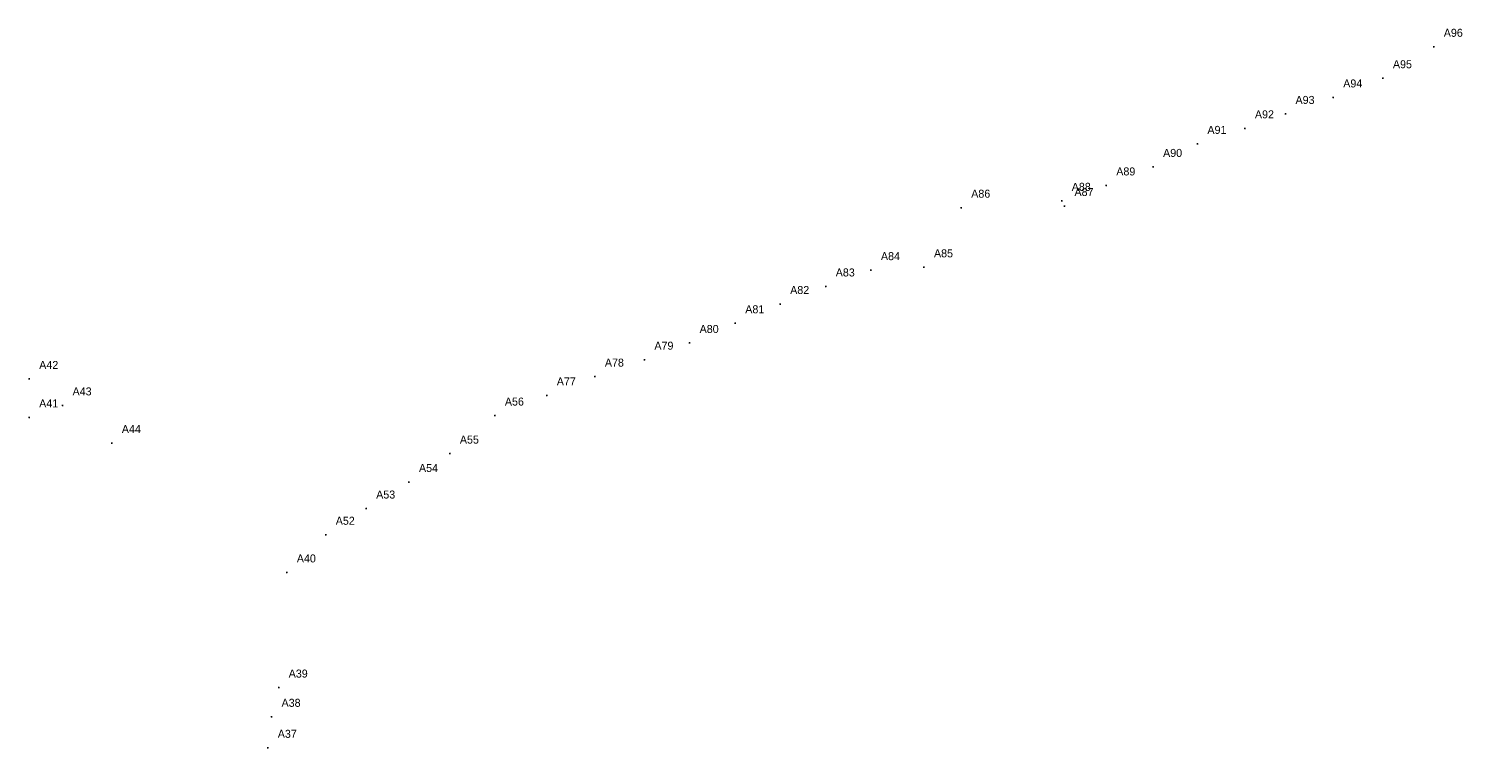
# Model space of a CAD drawing. Extents: x 1727960 to 1749562, y 651707 to 653731.
# Drawn here: x 1746276 to 1746993, y 652078 to 652437 of the extents above; entities that cross this region are included whole.
import ezdxf

# ---------------------------------------------------------------- set-up
doc = ezdxf.new("R2010")
doc.units = 0
doc.layers.add('SURVEY - DRAINAGE - Storm Sewer - Points - Locators', color=7, linetype='Continuous')
doc.layers.add('SURVEY - DRAINAGE - Storm Sewer - Points - Numbers', color=7, linetype='Continuous')

msp = doc.modelspace()

# ---------------------------------------------------------------- linework, layer by layer
at = {"layer": 'SURVEY - DRAINAGE - Storm Sewer - Points - Locators'}
for p, q in [((1746979.01, 652428.32), (1746978.51, 652428.32)), ((1746978.76, 652428.07), (1746978.76, 652428.57)), ((1746978.76, 652428.32), (1746978.76, 652428.32)), ((1746978.76, 652428.32), (1746978.76, 652428.32)), ((1746953.59, 652412.6), (1746953.09, 652412.6)), ((1746953.34, 652412.35), (1746953.34, 652412.85)), ((1746953.34, 652412.6), (1746953.34, 652412.6)), ((1746953.34, 652412.6), (1746953.34, 652412.6)), ((1746928.75, 652403.01), (1746928.25, 652403.01)), ((1746928.5, 652402.76), (1746928.5, 652403.26)), ((1746928.5, 652403.01), (1746928.5, 652403.01)), ((1746928.5, 652403.01), (1746928.5, 652403.01)), ((1746904.89, 652394.77), (1746904.39, 652394.77)), ((1746904.64, 652394.52), (1746904.64, 652395.02)), ((1746904.64, 652394.77), (1746904.64, 652394.77)), ((1746904.64, 652394.77), (1746904.64, 652394.77)), ((1746884.59, 652387.56), (1746884.09, 652387.56)), ((1746884.34, 652387.31), (1746884.34, 652387.81)), ((1746884.34, 652387.56), (1746884.34, 652387.56)), ((1746884.34, 652387.56), (1746884.34, 652387.56)), ((1746860.84, 652379.8), (1746860.34, 652379.8)), ((1746860.59, 652379.55), (1746860.59, 652380.05)), ((1746860.59, 652379.8), (1746860.59, 652379.8)), ((1746860.59, 652379.8), (1746860.59, 652379.8)), ((1746838.68, 652368.28), (1746838.18, 652368.28)), ((1746838.43, 652368.03), (1746838.43, 652368.53)), ((1746838.43, 652368.28), (1746838.43, 652368.28)), ((1746838.43, 652368.28), (1746838.43, 652368.28)), ((1746815.27, 652359.03), (1746814.77, 652359.03)), ((1746815.02, 652358.78), (1746815.02, 652359.28)), ((1746815.02, 652359.03), (1746815.02, 652359.03)), ((1746815.02, 652359.03), (1746815.02, 652359.03)), ((1746742.75, 652347.9), (1746742.25, 652347.9)), ((1746742.5, 652347.65), (1746742.5, 652348.15)), ((1746742.5, 652347.9), (1746742.5, 652347.9)), ((1746742.5, 652347.9), (1746742.5, 652347.9)), ((1746793.01, 652351.33), (1746792.51, 652351.33)), ((1746792.76, 652351.08), (1746792.76, 652351.58)), ((1746792.76, 652351.33), (1746792.76, 652351.33)), ((1746792.76, 652351.33), (1746792.76, 652351.33)), ((1746794.38, 652348.75), (1746793.88, 652348.75)), ((1746794.13, 652348.5), (1746794.13, 652349)), ((1746794.13, 652348.75), (1746794.13, 652348.75)), ((1746794.13, 652348.75), (1746794.13, 652348.75)), ((1746697.36, 652316.44), (1746697.36, 652316.94)), ((1746724.13, 652318.1), (1746723.63, 652318.1)), ((1746723.88, 652317.85), (1746723.88, 652318.35)), ((1746723.88, 652318.1), (1746723.88, 652318.1)), ((1746723.88, 652318.1), (1746723.88, 652318.1)), ((1746697.61, 652316.69), (1746697.11, 652316.69)), ((1746697.36, 652316.69), (1746697.36, 652316.69)), ((1746697.36, 652316.69), (1746697.36, 652316.69)), ((1746675.01, 652308.54), (1746674.51, 652308.54)), ((1746674.76, 652308.29), (1746674.76, 652308.79)), ((1746674.76, 652308.54), (1746674.76, 652308.54)), ((1746674.76, 652308.54), (1746674.76, 652308.54)), ((1746652.23, 652299.76), (1746651.73, 652299.76)), ((1746651.98, 652299.51), (1746651.98, 652300.01)), ((1746651.98, 652299.76), (1746651.98, 652299.76)), ((1746651.98, 652299.76), (1746651.98, 652299.76)), ((1746629.78, 652290.14), (1746629.28, 652290.14)), ((1746629.53, 652289.89), (1746629.53, 652290.39)), ((1746629.53, 652290.14), (1746629.53, 652290.14)), ((1746629.53, 652290.14), (1746629.53, 652290.14)), ((1746606.96, 652280.28), (1746606.46, 652280.28)), ((1746606.71, 652280.03), (1746606.71, 652280.53)), ((1746606.71, 652280.28), (1746606.71, 652280.28)), ((1746606.71, 652280.28), (1746606.71, 652280.28)), ((1746584.34, 652271.93), (1746583.84, 652271.93)), ((1746584.09, 652271.68), (1746584.09, 652272.18)), ((1746584.09, 652271.93), (1746584.09, 652271.93)), ((1746584.09, 652271.93), (1746584.09, 652271.93)), ((1746276.77, 652262.3), (1746276.27, 652262.3)), ((1746276.52, 652262.05), (1746276.52, 652262.55)), ((1746276.52, 652262.3), (1746276.52, 652262.3)), ((1746276.52, 652262.3), (1746276.52, 652262.3)), ((1746559.58, 652263.47), (1746559.08, 652263.47)), ((1746559.33, 652263.22), (1746559.33, 652263.72)), ((1746559.33, 652263.47), (1746559.33, 652263.47)), ((1746559.33, 652263.47), (1746559.33, 652263.47)), ((1746535.55, 652254.08), (1746535.05, 652254.08)), ((1746535.3, 652253.83), (1746535.3, 652254.33)), ((1746535.3, 652254.08), (1746535.3, 652254.08)), ((1746535.3, 652254.08), (1746535.3, 652254.08)), ((1746293.44, 652249.08), (1746292.94, 652249.08)), ((1746293.19, 652248.83), (1746293.19, 652249.33)), ((1746293.19, 652249.08), (1746293.19, 652249.08)), ((1746293.19, 652249.08), (1746293.19, 652249.08)), ((1746276.75, 652243.08), (1746276.25, 652243.08)), ((1746276.5, 652242.83), (1746276.5, 652243.33)), ((1746276.5, 652243.08), (1746276.5, 652243.08)), ((1746276.5, 652243.08), (1746276.5, 652243.08)), ((1746509.59, 652244), (1746509.09, 652244)), ((1746509.34, 652243.75), (1746509.34, 652244.25)), ((1746509.34, 652244), (1746509.34, 652244)), ((1746509.34, 652244), (1746509.34, 652244)), ((1746318.07, 652230.29), (1746317.57, 652230.29)), ((1746317.82, 652230.04), (1746317.82, 652230.54)), ((1746317.82, 652230.29), (1746317.82, 652230.29)), ((1746317.82, 652230.29), (1746317.82, 652230.29)), ((1746487.09, 652224.99), (1746486.59, 652224.99)), ((1746486.84, 652224.74), (1746486.84, 652225.24)), ((1746486.84, 652224.99), (1746486.84, 652224.99)), ((1746486.84, 652224.99), (1746486.84, 652224.99)), ((1746466.64, 652210.79), (1746466.14, 652210.79)), ((1746466.39, 652210.54), (1746466.39, 652211.04)), ((1746466.39, 652210.79), (1746466.39, 652210.79)), ((1746466.39, 652210.79), (1746466.39, 652210.79)), ((1746445.24, 652197.53), (1746444.74, 652197.53)), ((1746444.99, 652197.28), (1746444.99, 652197.78)), ((1746444.99, 652197.53), (1746444.99, 652197.53)), ((1746444.99, 652197.53), (1746444.99, 652197.53)), ((1746425.03, 652184.43), (1746424.53, 652184.43)), ((1746424.78, 652184.18), (1746424.78, 652184.68)), ((1746424.78, 652184.43), (1746424.78, 652184.43)), ((1746424.78, 652184.43), (1746424.78, 652184.43)), ((1746405.57, 652165.61), (1746405.07, 652165.61)), ((1746405.32, 652165.36), (1746405.32, 652165.86)), ((1746405.32, 652165.61), (1746405.32, 652165.61)), ((1746405.32, 652165.61), (1746405.32, 652165.61)), ((1746401.5, 652108.05), (1746401, 652108.05)), ((1746401.25, 652107.8), (1746401.25, 652108.3)), ((1746401.25, 652108.05), (1746401.25, 652108.05)), ((1746401.25, 652108.05), (1746401.25, 652108.05)), ((1746397.93, 652093.43), (1746397.43, 652093.43)), ((1746397.68, 652093.18), (1746397.68, 652093.68)), ((1746397.68, 652093.43), (1746397.68, 652093.43)), ((1746397.68, 652093.43), (1746397.68, 652093.43)), ((1746396.04, 652077.94), (1746395.54, 652077.94)), ((1746395.79, 652077.69), (1746395.79, 652078.19)), ((1746395.79, 652077.94), (1746395.79, 652077.94)), ((1746395.79, 652077.94), (1746395.79, 652077.94))]:
    msp.add_line(p, q, dxfattribs=at)

# ---------------------------------------------------------------- texts
at = {"layer": 'SURVEY - DRAINAGE - Storm Sewer - Points - Numbers'}
for s, p in [('A96', (1746983.76, 652433.32)), ('A95', (1746958.34, 652417.6)), ('A94', (1746933.5, 652408.01)), ('A93', (1746909.64, 652399.77)), ('A92', (1746889.34, 652392.56)), ('A91', (1746865.59, 652384.8)), ('A90', (1746843.43, 652373.28)), ('A89', (1746820.02, 652364.03)), ('A88', (1746797.76, 652356.33)), ('A86', (1746747.5, 652352.9)), ('A87', (1746799.13, 652353.75)), ('A84', (1746702.36, 652321.69)), ('A85', (1746728.88, 652323.1)), ('A83', (1746679.76, 652313.54)), ('A82', (1746656.98, 652304.76)), ('A81', (1746634.53, 652295.14)), ('A80', (1746611.71, 652285.28)), ('A79', (1746589.09, 652276.93)), ('A42', (1746281.52, 652267.3)), ('A78', (1746564.33, 652268.47)), ('A77', (1746540.3, 652259.08)), ('A43', (1746298.19, 652254.08)), ('A56', (1746514.34, 652249)), ('A41', (1746281.5, 652248.08)), ('A44', (1746322.82, 652235.29)), ('A55', (1746491.84, 652229.99)), ('A54', (1746471.39, 652215.79)), ('A53', (1746449.99, 652202.53)), ('A52', (1746429.78, 652189.43)), ('A40', (1746410.32, 652170.61)), ('A39', (1746406.25, 652113.05)), ('A38', (1746402.68, 652098.43)), ('A37', (1746400.79, 652082.94))]:
    msp.add_text(s, height=4, dxfattribs=at).set_placement(p)

doc.saveas('drawing.dxf')
